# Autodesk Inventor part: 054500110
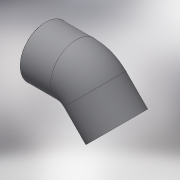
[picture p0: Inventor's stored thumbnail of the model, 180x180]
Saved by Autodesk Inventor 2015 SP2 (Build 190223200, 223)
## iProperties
Created: 2017-10
Part Number: 054500110
Material: Generic
Description: PLASSON 45° ELBOW CEMENT PVC 110
Document SubType Name: Modeling
Designer: KIM
Density: 1 g/cm^3
Appearance: Default
Author: KIM
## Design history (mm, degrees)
derived "054500.ipt"
feature "Solid1::054500.ipt"
tag "TaggingFeature1"
body "Solid1"
other parameters: "d1" = 129, "d5" = 99, "d7" = 1.1, "d9" = 129, "d13" = 135 deg, "d18" = 25, "d19" = 45 deg, "d21" = 61, "d22" = 0, "d24" = 135 deg, "d26" = 99, "d27" = 45 deg, "d28" = 86, "E_" = 129, "H_" = 35, "l_" = 61, "Z_" = 25
